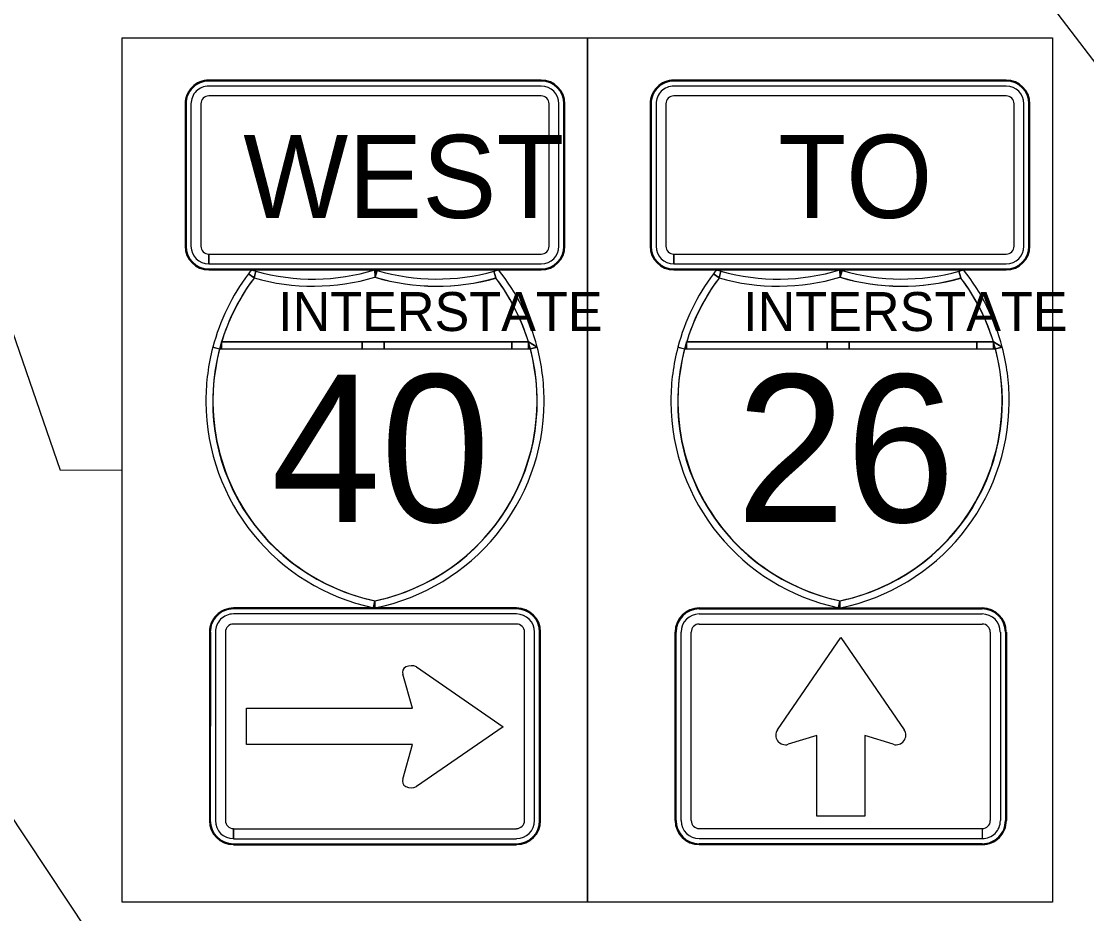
# Model space of a CAD drawing. Extents: x 886234 to 968767, y 455416 to 684046.
# Drawn here: x 916236 to 917582, y 512432 to 513561 of the extents above; entities that cross this region are included whole.
import ezdxf

# ---------------------------------------------------------------- set-up
doc = ezdxf.new("R2010")
doc.units = 0
for name, color, linetype in [('TC DEV SIGN BLACK 239', 7, 'Continuous'), ('TC DEV SIGN BLACK ZERO', 7, 'Continuous'), ('TC DEV SIGN WHITE', 7, 'Continuous'), ('TC LABEL TEXT', 7, 'Continuous')]:
    doc.layers.add(name, color=color, linetype=linetype)

msp = doc.modelspace()

# ---------------------------------------------------------------- linework, layer by layer
at = {"layer": 'TC DEV SIGN BLACK 239'}
for p, q in [((916893, 513479.1), (916473, 513479.1)), ((917480.7, 513479.1), (917060.7, 513479.1)), ((916893, 513466.6), (916473, 513466.6)), ((917480.7, 513466.6), (917060.7, 513466.6)), ((916450.5, 513456.6), (916450.5, 513276.6)), ((916463, 513456.6), (916463, 513276.6)), ((916903, 513276.6), (916903, 513456.6)), ((916915.5, 513276.6), (916915.5, 513456.6)), ((917038.2, 513456.6), (917038.2, 513276.6)), ((917050.7, 513456.6), (917050.7, 513276.6)), ((917490.7, 513276.6), (917490.7, 513456.6)), ((917503.2, 513276.6), (917503.2, 513456.6)), ((916473, 513254.1), (916473, 513266.6)), ((916473.1, 513266.6), (916893, 513266.6)), ((916473.1, 513266.6), (916473.1, 513254.1)), ((917060.7, 513254.1), (917060.7, 513266.6)), ((917060.8, 513266.6), (917480.7, 513266.6)), ((917060.8, 513266.6), (917060.8, 513254.1)), ((916473.1, 513254.1), (916893, 513254.1)), ((917060.8, 513254.1), (917480.7, 513254.1)), ((916861.9, 512811.5), (916504.1, 512811.5)), ((917092.8, 512811.5), (917450.5, 512811.5)), ((916481.3, 512788.7), (916481.3, 512550.2)), ((916494, 512788.7), (916494, 512550.2)), ((916861.9, 512798.8), (916504.1, 512798.8)), ((916872, 512550.2), (916872, 512788.7)), ((916884.7, 512550.2), (916884.7, 512788.7)), ((917070, 512550.2), (917069.9, 512788.7)), ((917082.6, 512550.2), (917082.6, 512788.7)), ((917092.8, 512798.8), (917450.5, 512798.8)), ((917460.7, 512788.7), (917460.7, 512550.2)), ((917473.4, 512788.7), (917473.4, 512550.2)), ((916730.5, 512692.3), (916718.1, 512735.5)), ((916735.3, 512744.7), (916845.2, 512668.9)), ((916520.6, 512646.4), (916520.6, 512692.3)), ((916520.6, 512692.3), (916730.5, 512692.3)), ((916845.2, 512668.9), (916735.3, 512593.2)), ((916730.5, 512646.4), (916520.6, 512646.4)), ((916718.1, 512602.4), (916730.5, 512646.4)), ((916504.1, 512527.3), (916504.1, 512540)), ((916504.2, 512540), (916861.9, 512540)), ((916504.2, 512540), (916504.2, 512527.3)), ((917450.4, 512540), (917092.8, 512540)), ((917450.4, 512540), (917450.4, 512527.3)), ((917450.6, 512527.3), (917450.6, 512540)), ((916504.2, 512527.3), (916861.9, 512527.3)), ((917450.4, 512527.3), (917092.8, 512527.3))]:
    msp.add_line(p, q, dxfattribs=at)
for points in [[(917191.6, 512665.2), (917271.7, 512781.8), (917351.7, 512665.2)], [(917191.6, 512665.2), (917271.7, 512781.8), (917351.7, 512665.2)], [(917191.6, 512665.2), (917271.7, 512781.8), (917351.7, 512665.2)], [(917241.3, 512555.8), (917241.3, 512658), (917205.3, 512646.7)], [(917241.3, 512555.8), (917241.3, 512658), (917205.3, 512646.7)], [(917241.3, 512555.8), (917241.3, 512658), (917205.3, 512646.7)], [(917338, 512646.7), (917302.1, 512658), (917302.1, 512555.8), (917241.3, 512555.8)], [(917338, 512646.7), (917302.1, 512658), (917302.1, 512555.8), (917241.3, 512555.8)], [(917338, 512646.7), (917302.1, 512658), (917302.1, 512555.8), (917241.3, 512555.8)]]:
    msp.add_lwpolyline(points, dxfattribs=at)
for centre, start, end in [((917201.7, 512658.3), 145.5508, 287.601), ((917201.7, 512658.3), 145.5508, 287.601), ((917201.7, 512658.3), 145.5508, 287.601), ((917341.7, 512658.3), 252.399, 34.4492), ((917341.7, 512658.3), 252.399, 34.4492), ((917341.7, 512658.3), 252.399, 34.4492)]:
    msp.add_arc(centre, 12.2, start, end, dxfattribs=at)
for centre, major_axis, ratio, start_param, end_param in [((916473, 513456.6), (22.5, 0), 0.999865, 1.570796, 3.141593), ((916893, 513456.6), (22.5, 0), 0.999865, 0, 1.570796), ((917060.7, 513456.6), (22.5, 0), 0.999865, 1.570796, 3.141593), ((917480.7, 513456.6), (22.5, 0), 0.999865, 0, 1.570796), ((916473, 513456.6), (10, 0), 0.999865, 1.570796, 3.141593), ((916893, 513456.6), (10, 0), 0.999865, 0, 1.570796), ((917060.7, 513456.6), (10, 0), 0.999865, 1.570796, 3.141593), ((917480.7, 513456.6), (10, 0), 0.999865, 0, 1.570796), ((916473, 513276.6), (22.5, 0), 0.999865, 3.141593, 4.712389), ((916473, 513276.6), (10, 0), 0.999865, 3.141593, 4.712389), ((916893, 513276.6), (22.5, 0), 0.999865, 4.712389, 6.283185), ((916893, 513276.6), (10, 0), 0.999865, 4.712389, 6.283185), ((917060.7, 513276.6), (22.5, 0), 0.999865, 3.141593, 4.712389), ((917060.7, 513276.6), (10, 0), 0.999865, 3.141593, 4.712389), ((917480.7, 513276.6), (22.5, 0), 0.999865, 4.712389, 6.283185), ((917480.7, 513276.6), (10, 0), 0.999865, 4.712389, 6.283185), ((916504.1, 512788.7), (22.8, 0), 0.999865, 1.570796, 3.141593), ((916861.9, 512788.7), (22.8, 0), 0.999865, 0, 1.570796), ((917092.8, 512788.7), (-22.8, 0), 0.999865, 4.712389, 6.283185), ((917450.5, 512788.7), (-22.8, 0), 0.999865, 3.141593, 4.712389), ((916504.1, 512788.7), (10.1, 0), 0.999865, 1.570796, 3.141593), ((916861.9, 512788.7), (10.1, 0), 0.999865, 0, 1.570796), ((917092.8, 512788.7), (-10.1, 0), 0.999865, 4.712389, 6.283185), ((917450.5, 512788.7), (-10.1, 0), 0.999865, 3.141593, 4.712389), ((916728.9, 512738), (11.3, 0), 0.720018, 0.96961, 3.452569), ((916728.9, 512599.9), (11.3, 0), 0.720018, 2.830617, 5.313577), ((916504.1, 512550.2), (22.8, 0), 0.999865, 3.141593, 4.712389), ((916504.1, 512550.2), (10.1, 0), 0.999865, 3.141593, 4.712389), ((916861.9, 512550.2), (22.8, 0), 0.999865, 4.712389, 6.283185), ((916861.9, 512550.2), (10.1, 0), 0.999865, 4.712389, 6.283185), ((917092.8, 512550.2), (-22.8, 0), 0.999865, 0, 1.570796), ((917092.8, 512550.2), (-10.1, 0), 0.999865, 0, 1.570796), ((917450.6, 512550.2), (-22.8, 0), 0.999865, 1.570796, 3.141593), ((917450.6, 512550.2), (-10.1, 0), 0.999865, 1.570796, 3.141593)]:
    msp.add_ellipse(centre, major_axis=major_axis, ratio=ratio, start_param=start_param, end_param=end_param, dxfattribs=at)
at = {"layer": 'TC DEV SIGN BLACK ZERO'}
for p, q in [((916893, 513486.6), (916473, 513486.6)), ((916473, 513485.4), (916473, 513485.4)), ((916893, 513485.4), (916473, 513485.4)), ((916893, 513485.4), (916893, 513485.4)), ((917480.7, 513486.6), (917060.7, 513486.6)), ((917060.7, 513485.4), (917060.7, 513485.4)), ((917480.7, 513485.4), (917060.7, 513485.4)), ((917480.7, 513485.4), (917480.7, 513485.4)), ((916443, 513456.6), (916443, 513276.6)), ((916444.2, 513456.6), (916444.2, 513276.6)), ((916444.2, 513456.6), (916444.2, 513456.6)), ((916921.8, 513456.6), (916921.8, 513456.6)), ((916921.8, 513276.6), (916921.8, 513456.6)), ((916923, 513276.6), (916923, 513456.6)), ((917030.7, 513456.6), (917030.7, 513276.6)), ((917031.9, 513456.6), (917031.9, 513276.6)), ((917031.9, 513456.6), (917031.9, 513456.6)), ((917509.5, 513456.6), (917509.5, 513456.6)), ((917509.5, 513276.6), (917509.5, 513456.6)), ((917510.7, 513276.6), (917510.7, 513456.6)), ((916444.2, 513276.6), (916444.2, 513276.6)), ((916921.8, 513276.6), (916921.8, 513276.6)), ((917031.9, 513276.6), (917031.9, 513276.6)), ((917509.5, 513276.6), (917509.5, 513276.6)), ((916473, 513246.6), (916473, 513247.9)), ((916473, 513247.9), (916473, 513247.9)), ((916473, 513247.9), (916893, 513247.9)), ((916473, 513247.9), (916473, 513246.6)), ((916473, 513246.6), (916893, 513246.6)), ((916683.2, 513237.3), (916683, 513246.6)), ((916683.2, 513238), (916683, 513246.6)), ((916893, 513247.9), (916893, 513247.9)), ((917060.7, 513246.6), (917060.7, 513247.9)), ((917060.7, 513247.9), (917060.7, 513247.9)), ((917060.7, 513247.9), (917480.7, 513247.9)), ((917060.7, 513247.9), (917060.7, 513246.6)), ((917060.7, 513246.6), (917480.7, 513246.6)), ((917271, 513237.3), (917270.7, 513246.6)), ((917270.9, 513238), (917270.7, 513246.6)), ((917480.7, 513247.9), (917480.7, 513247.9)), ((916530.2, 513236.4), (916532.6, 513244.9)), ((916833.4, 513244.9), (916835.8, 513236.4)), ((917117.9, 513236.4), (917120.3, 513244.9)), ((917421.1, 513244.9), (917423.5, 513236.4)), ((916489.2, 513155.5), (916876.9, 513155.5)), ((916666.7, 513155.5), (916489.2, 513155.5)), ((916694.8, 513155.5), (916666.7, 513155.5)), ((916855.9, 513155.5), (916694.8, 513155.5)), ((916876.9, 513155.5), (916855.9, 513155.5)), ((916888, 513148.8), (916876.9, 513155.5)), ((917076.9, 513155.5), (917464.6, 513155.5)), ((917254.4, 513155.5), (917076.9, 513155.5)), ((917282.5, 513155.5), (917254.4, 513155.5)), ((917443.6, 513155.5), (917282.5, 513155.5)), ((917464.6, 513155.5), (917443.6, 513155.5)), ((917475.7, 513148.8), (917464.6, 513155.5)), ((916486.6, 513146.6), (916879.4, 513146.6)), ((916486.6, 513146.6), (916489.2, 513146.6)), ((916489.2, 513146.6), (916666.7, 513146.6)), ((916666.7, 513146.6), (916694.8, 513146.6)), ((916694.8, 513146.6), (916855.9, 513146.6)), ((916855.9, 513146.6), (916876.9, 513146.6)), ((916879.2, 513147.2), (916876.9, 513146.6)), ((916876.9, 513146.6), (916879.4, 513146.6)), ((917074.4, 513146.6), (917467.1, 513146.6)), ((917074.4, 513146.6), (917076.9, 513146.6)), ((917076.9, 513146.6), (917254.4, 513146.6)), ((917254.4, 513146.6), (917282.5, 513146.6)), ((917282.5, 513146.6), (917443.6, 513146.6)), ((917443.6, 513146.6), (917464.6, 513146.6)), ((917466.9, 513147.2), (917464.6, 513146.6)), ((917464.6, 513146.6), (917467.1, 513146.6)), ((916469.3, 513082.2), (916469.3, 513079.6)), ((916896.8, 513079.5), (916896.8, 513082.3)), ((917057, 513082.2), (917057, 513079.6)), ((917484.5, 513079.5), (917484.5, 513082.3)), ((916861.9, 512819.1), (916504.1, 512819.1)), ((916504.1, 512817.9), (916504.1, 512817.9)), ((916861.9, 512817.9), (916504.1, 512817.9)), ((916683, 512819.1), (916683, 512828.2)), ((916861.9, 512817.9), (916861.9, 512817.9)), ((917092.8, 512819.1), (917450.5, 512819.1)), ((917092.8, 512817.9), (917450.5, 512817.9)), ((917092.8, 512817.9), (917092.8, 512817.9)), ((917270.7, 512819.1), (917270.7, 512828.2)), ((917450.5, 512817.9), (917450.5, 512817.9)), ((916473.7, 512788.7), (916473.7, 512550.2)), ((916475, 512788.7), (916474.9, 512550.2)), ((916475, 512788.7), (916475, 512788.7)), ((916891.1, 512788.7), (916891.1, 512788.7)), ((916891.1, 512550.2), (916891.1, 512788.7)), ((916892.3, 512550.2), (916892.3, 512788.7)), ((917062.4, 512550.2), (917062.3, 512788.7)), ((917063.6, 512788.7), (917063.6, 512788.7)), ((917063.6, 512550.2), (917063.6, 512788.7)), ((917479.7, 512788.7), (917479.7, 512550.2)), ((917479.7, 512788.7), (917479.7, 512788.7)), ((917481, 512788.7), (917481, 512550.2)), ((916475, 512550.2), (916474.9, 512550.2)), ((916891.1, 512550.2), (916891.1, 512550.2)), ((917063.6, 512550.2), (917063.6, 512550.2)), ((917479.7, 512550.2), (917479.7, 512550.2)), ((916504.1, 512519.7), (916504.1, 512521)), ((916504.1, 512521), (916504.1, 512521)), ((916504.1, 512521), (916861.9, 512521)), ((916504.1, 512521), (916504.1, 512519.7)), ((916504.1, 512519.7), (916861.9, 512519.7)), ((916861.9, 512521), (916861.9, 512521)), ((917092.8, 512521), (917092.8, 512521)), ((917450.5, 512521), (917092.8, 512521)), ((917450.5, 512519.7), (917092.8, 512519.7)), ((917450.5, 512521), (917450.5, 512519.7)), ((917450.6, 512519.7), (917450.6, 512521)), ((917450.6, 512521), (917450.6, 512521))]:
    msp.add_line(p, q, dxfattribs=at)
for points in [[(916526.9, 513246.6), (916526.9, 513246.6), (916526.9, 513246.6)], [(916683.2, 513246.6), (916683.2, 513238), (916685.7, 513245.8)], [(916839.2, 513246.6), (916839.2, 513246.6), (916839.2, 513246.6)], [(917114.6, 513246.6), (917114.6, 513246.6), (917114.6, 513246.6)], [(917270.9, 513246.6), (917270.9, 513238), (917273.4, 513245.8)], [(917426.9, 513246.6), (917426.9, 513246.6), (917426.9, 513246.6)], [(916523.1, 513241.7), (916530.2, 513236.4)], [(916530.2, 513236.4), (916523.1, 513241.7)], [(916532.6, 513244.9), (916530.2, 513236.4)], [(916683, 513237.3), (916683.2, 513238)], [(916685.7, 513245.8), (916683.2, 513237.3)], [(916835.8, 513236.4), (916833.4, 513244.9)], [(917110.8, 513241.7), (917117.9, 513236.4)], [(917117.9, 513236.4), (917110.8, 513241.7)], [(917120.3, 513244.9), (917117.9, 513236.4)], [(917270.7, 513237.3), (917270.9, 513238)], [(917273.4, 513245.8), (917271, 513237.3)], [(917423.5, 513236.4), (917421.1, 513244.9)], [(916489.2, 513155.5), (916489.2, 513146.6)], [(916489.2, 513146.6), (916489.2, 513155.5)], [(916666.7, 513146.6), (916666.7, 513155.5)], [(916666.7, 513155.5), (916666.7, 513146.6)], [(916694.8, 513155.5), (916694.8, 513146.6)], [(916694.8, 513146.6), (916694.8, 513155.5)], [(916855.9, 513146.6), (916855.9, 513155.5)], [(916855.9, 513155.5), (916855.9, 513146.6)], [(916876.9, 513155.5), (916888, 513148.8)], [(916876.9, 513146.6), (916876.9, 513155.5)], [(916876.9, 513155.5), (916876.9, 513146.6), (916879.2, 513147.2), (916876.9, 513155.5)], [(917076.9, 513155.5), (917076.9, 513146.6)], [(917076.9, 513146.6), (917076.9, 513155.5)], [(917254.4, 513146.6), (917254.4, 513155.5)], [(917254.4, 513155.5), (917254.4, 513146.6)], [(917282.5, 513155.5), (917282.5, 513146.6)], [(917282.5, 513146.6), (917282.5, 513155.5)], [(917443.6, 513146.6), (917443.6, 513155.5)], [(917443.6, 513155.5), (917443.6, 513146.6)], [(917464.6, 513155.5), (917475.7, 513148.8)], [(917464.6, 513146.6), (917464.6, 513155.5)], [(917464.6, 513155.5), (917464.6, 513146.6), (917466.9, 513147.2), (917464.6, 513155.5)], [(916478, 513148.8), (916486.6, 513146.6)], [(916486.6, 513146.5), (916478, 513148.8)], [(916879.4, 513146.6), (916879.2, 513147.2)], [(916888, 513148.8), (916879.4, 513146.6)], [(916879.4, 513146.6), (916888, 513148.8)], [(917065.7, 513148.8), (917074.4, 513146.6)], [(917074.3, 513146.5), (917065.7, 513148.8)], [(917467.1, 513146.6), (917466.9, 513147.2)], [(917475.7, 513148.8), (917467.1, 513146.6)], [(917467.1, 513146.6), (917475.7, 513148.8)], [(916681.2, 512819.5), (916683, 512828.2)], [(916683, 512828.2), (916681.2, 512819.5), (916683, 512819.1)], [(916683, 512828.2), (916683, 512819.1)], [(917268.9, 512819.5), (917270.7, 512828.2)], [(917270.7, 512828.2), (917268.9, 512819.5), (917270.7, 512819.1)], [(917270.7, 512828.2), (917270.7, 512819.1)]]:
    msp.add_lwpolyline(points, dxfattribs=at)
for centre, radius, start, end in [((916736.5, 513080.9), 267.2, 141.6709, 142.9968), ((916604.9, 513502.2), 267.2, 253.0099, 254.2907), ((916604.9, 513502.2), 267.2, 254.2907, 286.9893), ((916761.1, 513502.2), 267.2, 253.0588, 253.6206), ((916761.1, 513502.2), 267.2, 285.7093, 286.9901), ((916629.6, 513080.9), 267.2, 14.7231, 38.3291), ((917324.2, 513080.9), 267.2, 141.6709, 142.9968), ((917192.6, 513502.2), 267.2, 253.0099, 254.2907), ((917192.6, 513502.2), 267.2, 254.2907, 286.9893), ((917348.8, 513502.2), 267.2, 253.0588, 253.6206), ((917348.8, 513502.2), 267.2, 285.7093, 286.9901), ((917217.3, 513080.9), 267.2, 14.7231, 38.3291), ((916736.5, 513080.9), 267.2, 142.9968, 165.2769), ((916736.5, 513080.9), 258.3, 142.9968, 258.0595), ((916736.5, 513080.9), 258.3, 142.9968, 165.2769), ((916604.9, 513502.2), 276.1, 254.2907, 286.4259), ((916604.9, 513502.2), 276.1, 254.2907, 286.4259), ((916761.1, 513502.2), 276.1, 253.5741, 285.7093), ((916629.6, 513080.9), 258.3, 281.9405, 37.0032), ((916761.2, 513501.7), 275.7, 253.5731, 285.7093), ((916761.1, 513502.2), 267.2, 253.6206, 285.7093), ((916629.6, 513080.9), 258.3, 16.7759, 37.0032), ((917324.2, 513080.9), 267.2, 142.9968, 165.2769), ((917324.2, 513080.9), 258.3, 142.9968, 258.0595), ((917324.2, 513080.9), 258.3, 142.9968, 165.2769), ((917192.6, 513502.2), 276.1, 254.2907, 286.4259), ((917192.6, 513502.2), 276.1, 254.2907, 286.4259), ((917348.8, 513502.2), 276.1, 253.5741, 285.7093), ((917217.3, 513080.9), 258.3, 281.9405, 37.0032), ((917348.9, 513501.7), 275.7, 253.5731, 285.7093), ((917348.8, 513502.2), 267.2, 253.6206, 285.7093), ((917217.3, 513080.9), 258.3, 16.7759, 37.0032), ((916736.5, 513080.9), 258.3, 163.2241, 165.2769), ((916629.6, 513080.9), 258.3, 14.7231, 16.7759), ((917324.2, 513080.9), 258.3, 163.2241, 165.2769), ((917217.3, 513080.9), 258.3, 14.7231, 16.7759), ((916736.5, 513080.9), 267.2, 165.2769, 179.7177), ((916735.2, 513080.1), 257.3, 165.0438, 258.3001), ((916630.8, 513080.1), 257.3, 281.7196, 14.964), ((916629.6, 513080.9), 267.2, 0.2997, 14.7231), ((917324.2, 513080.9), 267.2, 165.2769, 179.7177), ((917322.9, 513080.1), 257.3, 165.0438, 258.3001), ((917218.6, 513080.1), 257.3, 281.7196, 14.964), ((917217.3, 513080.9), 267.2, 0.2997, 14.7231), ((916736.5, 513080.9), 267.2, 180.2823, 258.0591), ((916629.6, 513080.9), 267.2, 281.537, 359.7003), ((917324.2, 513080.9), 267.2, 180.2823, 258.0591), ((917217.3, 513080.9), 267.2, 281.537, 359.7003), ((916629.6, 513080.9), 258.3, 281.9405, 281.9604), ((916736.5, 513080.9), 267.2, 258.458, 258.463), ((916629.6, 513080.9), 267.2, 281.5369590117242, 281.53700435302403), ((917217.3, 513080.9), 258.3, 281.9405, 281.9604), ((917324.2, 513080.9), 267.2, 258.458, 258.463), ((917217.3, 513080.9), 267.2, 281.5369590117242, 281.53700435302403)]:
    msp.add_arc(centre, radius, start, end, dxfattribs=at)
for centre, major_axis, start_param, end_param in [((916473, 513456.6), (30, 0), 1.570796, 3.141593), ((916473, 513456.6), (28.8, 0), 1.570796, 3.141593), ((916893, 513456.6), (30, 0), 0, 1.570796), ((916893, 513456.6), (28.8, 0), 0, 1.570796), ((917060.7, 513456.6), (30, 0), 1.570796, 3.141593), ((917060.7, 513456.6), (28.8, 0), 1.570796, 3.141593), ((917480.7, 513456.6), (30, 0), 0, 1.570796), ((917480.7, 513456.6), (28.8, 0), 0, 1.570796), ((916473, 513276.6), (30, 0), 3.141593, 4.712389), ((916473, 513276.6), (28.8, 0), 3.141593, 4.712389), ((916893, 513276.6), (30, 0), 4.712389, 6.283185), ((916893, 513276.6), (28.8, 0), 4.712389, 6.283185), ((917060.7, 513276.6), (30, 0), 3.141593, 4.712389), ((917060.7, 513276.6), (28.8, 0), 3.141593, 4.712389), ((917480.7, 513276.6), (30, 0), 4.712389, 6.283185), ((917480.7, 513276.6), (28.8, 0), 4.712389, 6.283185), ((916504.1, 512788.7), (30.4, 0), 1.570796, 3.141593), ((916504.1, 512788.7), (29.2, 0), 1.570796, 3.141593), ((916861.9, 512788.7), (30.4, 0), 0, 1.570796), ((916861.9, 512788.7), (29.2, 0), 0, 1.570796), ((917092.8, 512788.7), (-30.4, 0), 4.712389, 6.283185), ((917092.8, 512788.7), (-29.2, 0), 4.712389, 6.283185), ((917450.5, 512788.7), (-30.4, 0), 3.141593, 4.712389), ((917450.5, 512788.7), (-29.2, 0), 3.141593, 4.712389), ((916504.1, 512550.2), (30.4, 0), 3.141593, 4.712389), ((916504.1, 512550.2), (29.2, 0), 3.141593, 4.712389), ((916861.9, 512550.2), (30.4, 0), 4.712389, 6.283185), ((916861.9, 512550.2), (29.2, 0), 4.712389, 6.283185), ((917092.8, 512550.2), (-30.4, 0), 0, 1.570796), ((917092.8, 512550.2), (-29.2, 0), 0, 1.570796), ((917450.6, 512550.2), (-30.4, 0), 1.570796, 3.141593), ((917450.6, 512550.2), (-29.2, 0), 1.570796, 3.141593)]:
    msp.add_ellipse(centre, major_axis=major_axis, ratio=0.999865, start_param=start_param, end_param=end_param, dxfattribs=at)
at = {"layer": 'TC DEV SIGN WHITE'}
for p, q in [((916893, 513486.6), (916473, 513486.6)), ((917480.7, 513486.6), (917060.7, 513486.6)), ((916443, 513456.6), (916443, 513276.6)), ((916923, 513276.6), (916923, 513456.6)), ((917030.7, 513456.6), (917030.7, 513276.6)), ((917510.7, 513276.6), (917510.7, 513456.6)), ((916473, 513246.6), (916893, 513246.6)), ((917060.7, 513246.6), (917480.7, 513246.6)), ((916861.9, 512819.1), (916504.1, 512819.1)), ((917092.8, 512819.1), (917450.5, 512819.1)), ((916473.7, 512788.7), (916473.7, 512550.2)), ((916892.3, 512550.2), (916892.3, 512788.7)), ((917062.4, 512550.2), (917062.3, 512788.7)), ((917481, 512788.7), (917481, 512550.2)), ((916504.1, 512519.7), (916861.9, 512519.7)), ((917450.6, 512519.7), (917092.8, 512519.7))]:
    msp.add_line(p, q, dxfattribs=at)
for centre, major_axis, start_param, end_param in [((916473, 513456.6), (30, 0), 1.570796, 3.141593), ((916893, 513456.6), (30, 0), 0, 1.570796), ((917060.7, 513456.6), (30, 0), 1.570796, 3.141593), ((917480.7, 513456.6), (30, 0), 0, 1.570796), ((916473, 513276.6), (30, 0), 3.141593, 4.712389), ((916893, 513276.6), (30, 0), 4.712389, 6.283185), ((917060.7, 513276.6), (30, 0), 3.141593, 4.712389), ((917480.7, 513276.6), (30, 0), 4.712389, 6.283185), ((916504.1, 512788.7), (30.4, 0), 1.570796, 3.141593), ((916861.9, 512788.7), (30.4, 0), 0, 1.570796), ((917092.8, 512788.7), (-30.4, 0), 4.712389, 6.283185), ((917450.5, 512788.7), (-30.4, 0), 3.141593, 4.712389), ((916504.1, 512550.2), (30.4, 0), 3.141593, 4.712389), ((916861.9, 512550.2), (30.4, 0), 4.712389, 6.283185), ((917092.8, 512550.2), (-30.4, 0), 0, 1.570796), ((917450.6, 512550.2), (-30.4, 0), 1.570796, 3.141593)]:
    msp.add_ellipse(centre, major_axis=major_axis, ratio=0.999865, start_param=start_param, end_param=end_param, dxfattribs=at)
at = {"layer": 'TC LABEL TEXT'}
for points in [[(917057.6, 514176.4), (917138.1, 514097.6), (917190.4, 514043.6), (917358.5, 513815.8), (917633.5, 513455.2), (917812, 513256.3), (918045.7, 513101.4), (918174.4, 512997.9), (918422.4, 512811.2), (918567.4, 512700.5), (918873.9, 512444.5), (918961.7, 512391)], [(916363.7, 512993.5), (916285.7, 512993.1), (915883.6, 514159.5)], [(917530.2, 511638.4), (916833.8, 511635.4), (915652, 513417.9)]]:
    msp.add_lwpolyline(points, dxfattribs=at)
for points in [[(916363.7, 513540), (916951.4, 513540), (916951.4, 512446.9), (916363.7, 512446.9)], [(916951.4, 513540), (917539.1, 513540), (917539.1, 512446.9), (916951.4, 512446.9)]]:
    msp.add_lwpolyline(points, close=True, dxfattribs=at)

# ---------------------------------------------------------------- texts
at = {"layer": 'TC DEV SIGN BLACK 239'}
for s, p in [('WEST', (916516.6, 513312.3)), ('TO', (917192.6, 513312.3))]:
    msp.add_text(s, height=105, rotation=360, dxfattribs=at).set_placement(p)
at = {"layer": 'TC DEV SIGN BLACK ZERO'}
for s, height, p in [('INTERSTATE', 49.28, (916560.6, 513169.3)), ('INTERSTATE', 49.28, (917148.3, 513169.3)), ('40', 186.16, (916551.7, 512927.9)), ('26', 186.16, (917139.4, 512927.9))]:
    msp.add_text(s, height=height, rotation=360, dxfattribs=at).set_placement(p)
at = {"layer": 'TC LABEL TEXT'}
msp.add_text('-Y8- HOMINY CREEK RD', height=125, rotation=318.9754, dxfattribs=at).set_placement((917428.9, 513795.9))

doc.saveas('drawing.dxf')
